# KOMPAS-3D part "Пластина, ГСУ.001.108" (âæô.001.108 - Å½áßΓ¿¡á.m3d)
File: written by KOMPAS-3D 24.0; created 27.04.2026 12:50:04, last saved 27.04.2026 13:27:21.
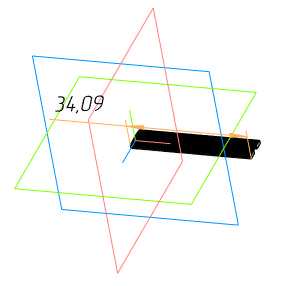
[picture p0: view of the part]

Document properties: Автор: User7; Полное имя файла: C:\Users\User7\Desktop\Двигатель мясорубки\ГСУ.001.108 - Пластина.m3d

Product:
- Part/product: Пластина  | designation ГСУ.001.108
    Масса: 0.00166

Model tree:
1. Эскиз:1
2. Элемент выдавливания:1
     Расстояние 1 = 0.3
3. Массив по сетке:1  (with: Элемент выдавливания:1, Эскиз:1)  (110 pattern instances)
     Шаг 1 = 0.31; Угол раствора = 90
4. Линейный размер:1  (with: Грань.Массив по сетке:1, Грань.Элемент выдавливания:1)
     Значение = 34.09

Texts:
  ГСУ.001.108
